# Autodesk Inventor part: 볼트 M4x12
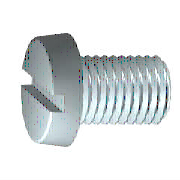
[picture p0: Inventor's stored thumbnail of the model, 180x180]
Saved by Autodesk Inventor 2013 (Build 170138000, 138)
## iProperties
Created: 2012-02
Part Number: 볼트 M4x12
Material: 강철, 연강
Description: 6각머리 태핑 나사
Document SubType Name: Modeling
Standard: KS B 1021
Designer: mduedu
Standards Organization: KS
Language: ko-KR
Size Designation: A  M 4 x 12
Categories: <MemberInstance><Categories><Category DisplayName="조임쇠" InternalName="e4da775c-781d-43d5-af7c-5136215cf5a6" Mnemonic="FSTN"><Category DisplayName="볼트" InternalN
Density: 1 g/cm^3
IsCustomPart: 0
Author: mduedu
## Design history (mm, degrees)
body "Solid1"
revolve "본체" stored, may be unused: angle "d8" = 90 deg
sketch "스케치2"
  geometry: L1 (0, 0)-(0, 3.273) reference; L2 (-3.5, 0.6)-(3.5, 0.6); L3 (3.5, 0.6)-(3.5, -0.6); L4 (3.5, -0.6)-(-3.5, -0.6); L5 (-3.5, -0.6)-(-3.5, 0.6); L6 (-3.5, 0)-(3.5, 0); L7 (0, 0.6)-(0, -0.6); C1 r 3.5 at (0, 0) reference; 1 further point
  constraints: 12 end point, 5 midpoint, 2 parallel, 1 collinear, 1 horizontal, 1 perpendicular
  dimensions: "d11" = 1.2 distance of L4.end L2.start (= SBR); "d12" = 7 distance of L2.start L2.end (= KOD)
fillet "모깎기1" dims "d14" = 0.2 (= RR)
extrude "슬롯" cut sketch "스케치2" distance "d19" = 1.1 (= STI); taper "d20" = 0 deg
feature "스레드" dims "d15" = 10.6 (= GEL), "d16" = 0
chamfer "모따기1" distance "d17" = 0.42941 (= -0.5 x SPD + 0.5 x GD); stored, may be unused: second distance "d18" = 0.42952 (computed from GUL), angle "d36" = 45 deg
workplane "Work Plane1"
sketch "스케치1"
  geometry: L1 (-2.6, 0)-(12, 0); L2 (12, 0)-(12, 2); L3 (12, 2)-(1.4, 2); L4 (1.4, 2)-(0.97, 1.785); L5 (0.97, 1.785)-(0, 1.785); L6 (0, 1.785)-(0, 3.5); L7 (-5.52, 0)-(14.92, 0) reference; L8 (0, -0.7)-(0, 4.2) reference; L9 (-2.6, 0)-(-2.6, 3.273); L10 (0, 3.5)-(-2.6, 3.273); L11 (1.4, 2)-(0, 2)
  constraints: 18 end point, 4 parallel, 2 collinear, 2 perpendicular, 1 horizontal, 1 point on line
  dimensions: "d0" = 12 distance between parallel lines of L2 L6 (= NLG); "d1" = 10.6 distance from line of L3.end L2 (= GEL); "d2" = 0.42952 horizontal distance of L4.end L3.end (computed from GAL); "d3" = 2.6 distance from line of L1.start L6 (= KOH); "d4" = 4 diameter of L3 L1 (= GD); "d5" = 3.5705 diameter of L5 L1 (= BDM); "d9" = 7 diameter of L6.end L1 (= KOD); "d10" = 5 deg angle of L10 L1 (= KEWI)
other parameters: "GD" = 4 (= NND) [user parameter; used in 2 equation terms], "NLG" = 12 [user parameter; used in 1 equation term], "GEL" = 10.6 [user parameter; used in 2 equation terms], "KOD" = 7 [user parameter; used in 2 equation terms], "KOH" = 2.6 [user parameter; used in 1 equation term], "GAL" = 0.42941 (= 0.61345 x PTC) [user parameter; used in 1 equation term], "SPD" = 3.14117 (= NND - 1.2269 x PTC) [user parameter; used in 1 equation term], "BDM" = 3.5705 [user parameter; used in 1 equation term], "GUL" = 0.42941 (= 0.61345 x PTC) [user parameter; used in 1 equation term], "RR" = 0.2 [user parameter; used in 1 equation term], "d7" = 0, "SBR" = 1.2 [user parameter; used in 1 equation term], "STI" = 1.1 [user parameter; used in 1 equation term], "KEWI" = 5 deg [user parameter; used in 1 equation term], "d37" = 0, "d39" = 0, "PTC" = 0.7 [user parameter; used in 5 equation terms], "THREADDIA" = 4 [user parameter; used in 1 equation term], "TOA" = 30 deg [user parameter], "TPU" = 14.28571 (computed from PTC) [user parameter], "NND" = 4 [user parameter; used in 2 equation terms], "GD1" = 3.14117 (= THREADDIA - 1.2269 x PTC) [user parameter]
